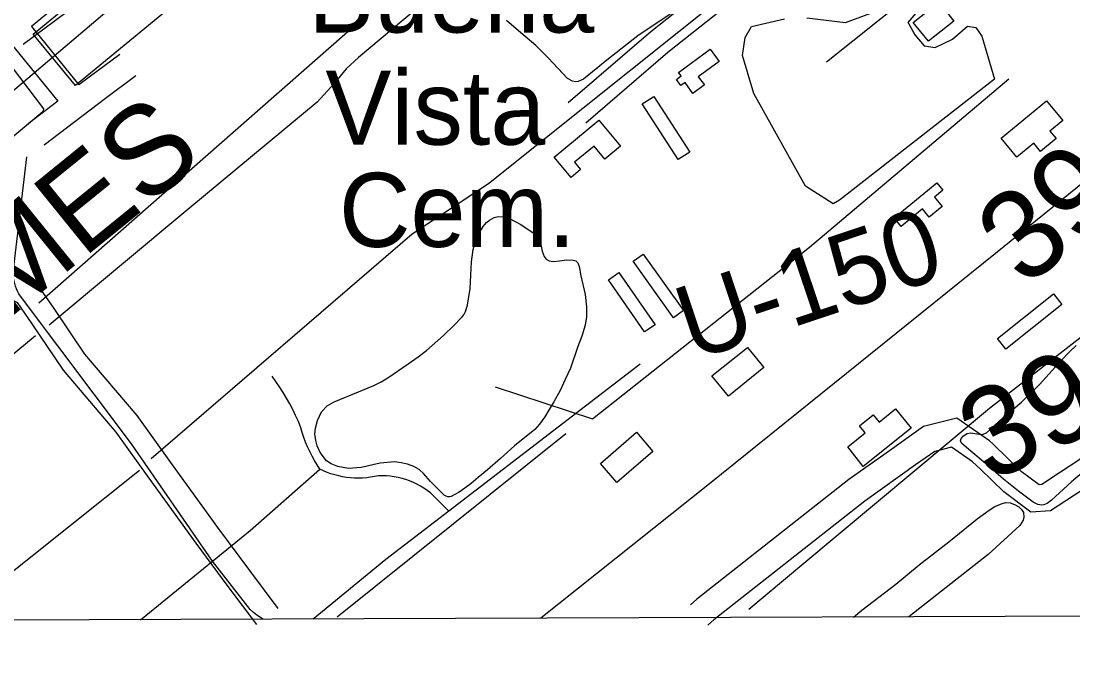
# Model space of a CAD drawing. Extents: x 3392644 to 3430565, y 576657 to 602123.
# Drawn here: x 3410265 to 3411444, y 582044 to 582765 of the extents above; entities that cross this region are included whole.
import ezdxf

# ---------------------------------------------------------------- set-up
doc = ezdxf.new("R2010")
doc.units = 0
for name, color, linetype in [('V-BLDG-OTLN', 7, 'Continuous'), ('V-DTCH-CNTR', 7, 'Continuous'), ('V-GRID-FRAM', 7, 'Continuous'), ('V-RIVR-RANG-IDEN', 7, 'Continuous'), ('V-ROAD-CNTR', 7, 'Continuous'), ('V-SITE-OTLN', 7, 'Continuous'), ('V-SITE-OTLN-IDEN', 7, 'Continuous'), ('V-SITE-VEGE', 7, 'Continuous'), ('V-SURV-IDEN', 7, 'Continuous'), ('V-TOPO-BNDY', 7, 'Continuous'), ('V-TOPO-GNAM-IDEN', 7, 'Continuous'), ('V-TOPO-SHOR', 7, 'Continuous')]:
    doc.layers.add(name, color=color, linetype=linetype)

msp = doc.modelspace()

# ---------------------------------------------------------------- linework, layer by layer
at = {"layer": 'V-BLDG-OTLN'}
for points in [[(3411265.3, 582763.1), (3411293.8, 582785.7), (3411310.7, 582764.5), (3411282.2, 582741.9)], [(3411002.2, 582707), (3411037.6, 582732.9), (3411047.6, 582719.3), (3411024.3, 582702.2), (3411031.1, 582692.9), (3411018.3, 582683.5), (3411009.4, 582695.6), (3411004.9, 582692.3), (3410999.9, 582699.1), (3411005.1, 582703)], [(3410974.3, 582680.2), (3411014.7, 582617.8), (3411001.9, 582609.5), (3410961.5, 582671.9)], [(3411363.9, 582633.2), (3411414.7, 582675.2), (3411432.9, 582653.2), (3411418.4, 582641.2), (3411425.4, 582632.8), (3411408.1, 582618.5), (3411400.5, 582627.7), (3411381.4, 582612)], [(3410862.8, 582612.1), (3410912.9, 582653.4), (3410936.9, 582624.4), (3410919.4, 582609.9), (3410907.4, 582624.4), (3410885.6, 582606.4), (3410892.3, 582598.2), (3410881.6, 582589.3)], [(3411243.7, 582544), (3411291.7, 582583.3), (3411298.5, 582575.1), (3411289.1, 582567.4), (3411297.7, 582556.9), (3411283, 582544.9), (3411275.6, 582554), (3411251.6, 582534.3)], [(3410962.4, 582503.3), (3411007.6, 582440.1), (3410996.6, 582432.2), (3410951.4, 582495.4)], [(3410935.3, 582482.7), (3410975.9, 582424.4), (3410964, 582416.2), (3410923.5, 582474.5)], [(3411431.8, 582447.1), (3411369.2, 582397.1), (3411359.9, 582408.8), (3411422.5, 582458.8)], [(3411039.6, 582367), (3411079.3, 582399), (3411097.6, 582376.3), (3411058, 582344.3)], [(3411262.8, 582308.3), (3411209.2, 582265.7), (3411191.8, 582287.6), (3411211.2, 582303.1), (3411205, 582310.9), (3411220.5, 582323.3), (3411226.9, 582315.3), (3411245.4, 582330.1)], [(3410914.5, 582269), (3410954.9, 582303.8), (3410973.3, 582282.4), (3410932.9, 582247.7)]]:
    msp.add_lwpolyline(points, close=True, dxfattribs=at)
at = {"layer": 'V-DTCH-CNTR'}
for points in [[(3410536.1, 582094.4), (3410533.3, 582096.2), (3410529.4, 582099), (3410525.6, 582102), (3410521.9, 582105.2), (3410479.7, 582159.4), (3410388.7, 582290.8), (3410264.4, 582456.4), (3410262.7, 582459.1), (3410261.2, 582461.8), (3410259.9, 582464.6), (3410258.8, 582467.5), (3410257.9, 582470.4), (3410257.2, 582473.5), (3410256.7, 582476.5), (3410256.4, 582479.6), (3410256.3, 582482.7), (3410256.4, 582485.8), (3410256.8, 582488.9), (3410257.3, 582492), (3410271.4, 582612.6)], [(3410959.1, 582380.1), (3410744.8, 582215.6), (3410673.9, 582161.2), (3410592.6, 582094.6)], [(3410744.8, 582215.6), (3410724, 582236.1), (3410720.4, 582238.8), (3410716.7, 582241.3), (3410712.9, 582243.6), (3410708.9, 582245.7), (3410704.9, 582247.7), (3410700.7, 582249.4), (3410696.5, 582250.9), (3410692.2, 582252.2), (3410687.9, 582253.2), (3410683.5, 582254.1), (3410679, 582254.7), (3410674.6, 582255.1), (3410670.1, 582255.2), (3410665.6, 582255.2), (3410661.2, 582254.2), (3410656.8, 582253.5), (3410652.3, 582252.9), (3410647.9, 582252.6), (3410643.4, 582252.5), (3410638.9, 582252.5), (3410634.4, 582252.8), (3410630, 582253.3), (3410625.5, 582254), (3410621.2, 582254.9), (3410616.8, 582256), (3410612.5, 582257.4), (3410608.3, 582258.9), (3410604.2, 582260.6), (3410600.1, 582262.4), (3410597, 582267.2), (3410594, 582272.1), (3410591.3, 582277.2), (3410588.7, 582282.3), (3410586.3, 582287.5), (3410584.1, 582292.7), (3410582.1, 582298.1), (3410580.3, 582303.5), (3410578.7, 582309), (3410575.9, 582315.9), (3410572.9, 582322.6), (3410569.7, 582329.2), (3410566.3, 582335.7), (3410562.7, 582342.2), (3410558.9, 582348.5), (3410554.9, 582354.7), (3410550.8, 582360.7), (3410546.4, 582366.7)], [(3410399, 582093.9), (3410479.7, 582159.4), (3410522, 582193.7), (3410600.1, 582262.4)]]:
    msp.add_lwpolyline(points, dxfattribs=at)
at = {"layer": 'V-GRID-FRAM'}
msp.add_lwpolyline([(3396720.3, 600227.7), (3428325.7, 600342.6), (3428399.7, 582159.3), (3396778.5, 582044.3), (3396720.3, 600227.7)], dxfattribs=at)
at = {"layer": 'V-ROAD-CNTR'}
for points in [[(3411723.4, 583955), (3411553, 583820.8), (3411271, 583581.5), (3410931.3, 583299.4), (3410595.8, 583021.3), (3410276.6, 582758.6)], [(3411352.3, 583060), (3411234.7, 582961.1), (3410970.9, 582752.3), (3410878.5, 582672.9)], [(3411373.6, 583038.8), (3411253.7, 582937.9), (3410990, 582729.2), (3410898.1, 582650.2)], [(3411902.5, 582930.5), (3411896.5, 582928.3), (3411890.5, 582925.8), (3411884.7, 582923.2), (3411879, 582920.4), (3411873.3, 582917.3), (3411867.8, 582914.1), (3411862.4, 582910.7), (3411857.1, 582907.1), (3411851.9, 582903.4), (3411846.8, 582899.4), (3411841.9, 582895.3), (3411773.2, 582840.3), (3411704.7, 582785.1), (3411636.2, 582729.7), (3411567.9, 582674.2), (3411357.5, 582504), (3411036.7, 582246), (3410847.9, 582095.5)], [(3410148.2, 582867.3), (3410211, 582791.7), (3410306.1, 582674.7)], [(3410276.6, 582758.6), (3410329.9, 582692.9)], [(3410375.8, 582727.1), (3410341.5, 582701.8), (3410329.9, 582692.9)], [(3410393.6, 582703), (3410359.6, 582677.8), (3410291.1, 582625.5)], [(3410306.1, 582674.7), (3410272.9, 582649.4)], [(3410203.4, 582535.8), (3410214.1, 582516.5), (3410225.2, 582497.7), (3410250.9, 582488.1), (3410281.1, 582472.2), (3410301.9, 582442.5), (3410336.2, 582391.5), (3410394.8, 582322.6), (3410432.7, 582270.1), (3410485.2, 582197.3), (3410521, 582149), (3410552.9, 582106.5)], [(3410177.1, 582521.3), (3410188, 582501.5), (3410204.8, 582473.3), (3410238.6, 582460.7), (3410260.7, 582449.1), (3410277.2, 582425.5), (3410312.3, 582373.3), (3410371.2, 582304), (3410408.4, 582252.6), (3410461, 582179.6), (3410496.9, 582131.1), (3410528.9, 582088.5)], [(3411635.1, 582423.7), (3411614.9, 582408.5), (3411523.6, 582332.9), (3411450.8, 582272.5), (3411430.3, 582259)], [(3411354.7, 582290.5), (3411350.8, 582294.2), (3411314.2, 582319.5), (3411276.7, 582310.2), (3411238.5, 582283.1)], [(3411340.6, 582262.4), (3411331.8, 582270.8), (3411308.2, 582287.1), (3411289.4, 582282.5), (3411267.9, 582267.2)], [(3411430.3, 582259), (3411409.4, 582245.2), (3411406.4, 582245), (3411386.3, 582260), (3411354.7, 582290.5)], [(3411238.5, 582283.1), (3411193, 582250.8), (3411022.7, 582116.8), (3411015.5, 582110.7)], [(3411267.9, 582267.2), (3411211, 582226.8), (3411041.6, 582093.6), (3411034.8, 582087.8)], [(3411454.5, 582239), (3411419.1, 582215.7), (3411397.1, 582214.5), (3411366.9, 582237.1), (3411340.6, 582262.4)]]:
    msp.add_lwpolyline(points, dxfattribs=at)
at = {"layer": 'V-SITE-OTLN'}
msp.add_lwpolyline([(3410910, 583172.6), (3410326.2, 582692.2), (3410278.8, 582750), (3410866.1, 583232.3)], close=True, dxfattribs=at)
at = {"layer": 'V-SITE-VEGE'}
for p, q in [((3411364.8, 582224.1), (3411369, 582225.1)), ((3411369, 582225.1), (3411373.8, 582224.9)), ((3411373.8, 582224.9), (3411378.7, 582223.1)), ((3411336.9, 582206.9), (3411350.3, 582216.7)), ((3411350.3, 582216.7), (3411356.6, 582220.8)), ((3411356.6, 582220.8), (3411364.8, 582224.1)), ((3411378.7, 582223.1), (3411383.6, 582220.4)), ((3411383.6, 582220.4), (3411386.8, 582217.4)), ((3411386.8, 582217.4), (3411388.8, 582213.8)), ((3411388.8, 582213.8), (3411389.4, 582208.8)), ((3411305, 582181.2), (3411336.9, 582206.9)), ((3411388.4, 582205.4), (3411384.7, 582199.3)), ((3411389.4, 582208.8), (3411388.4, 582205.4)), ((3411384.7, 582199.3), (3411349.3, 582166.8)), ((3411271.9, 582155.2), (3411305, 582181.2)), ((3411349.3, 582166.8), (3411260.2, 582097)), ((3411245.7, 582133.6), (3411271.9, 582155.2)), ((3411207.5, 582104.4), (3411245.7, 582133.6)), ((3411198.2, 582096.8), (3411207.5, 582104.4)), ((3411260.2, 582097), (3411198.2, 582096.8))]:
    msp.add_line(p, q, dxfattribs=at)
for points in [[(3411296.9, 582807.3), (3411259.1, 582763), (3411260.4, 582761.6), (3411267, 582749.1), (3411277.7, 582736.6), (3411289.9, 582735), (3411309.2, 582744.2), (3411326, 582758.8), (3411335.5, 582757.3), (3411342.1, 582747.6), (3411356.2, 582699.5), (3411182.5, 582563.7), (3411175.6, 582559.7), (3411144.6, 582579.5), (3411086.6, 582683.2), (3411073.8, 582725.8), (3411077, 582746.2), (3411084.1, 582758.4), (3411121.1, 582767.2)], [(3411013.3, 582785.7), (3410972.6, 582758.9), (3410956.6, 582748.1), (3410921.6, 582720.9), (3410895.6, 582699.5), (3410889.8, 582697), (3410886.8, 582696.6), (3410883.1, 582697.1), (3410877.5, 582700.1), (3410856.4, 582723), (3410842.1, 582737.1), (3410825.4, 582751.5), (3410809.3, 582765.2)], [(3411145.8, 582768), (3411189.4, 582763), (3411239, 582781.1)], [(3411488.3, 582286.8), (3411442.8, 582248.3), (3411420.1, 582227.9), (3411415.4, 582224), (3411411.5, 582222.5), (3411409.5, 582222.1), (3411404.9, 582223), (3411399.7, 582225.4), (3411383.2, 582237.8), (3411366.5, 582251.5), (3411346.1, 582268.8), (3411324.8, 582286.8), (3411319.3, 582291.7), (3411318.4, 582294.1), (3411318.9, 582296.7), (3411321.6, 582299.7), (3411325.6, 582302.4), (3411330, 582303.4), (3411336.4, 582302.2), (3411342.7, 582301.2), (3411347.3, 582303.2), (3411350.8, 582306.2), (3411356.8, 582312), (3411365.6, 582320.2), (3411386.5, 582337.7), (3411406.9, 582357.2), (3411421, 582373.2), (3411431.2, 582384.4), (3411440.3, 582393.8), (3411448.1, 582401.1)]]:
    msp.add_lwpolyline(points, dxfattribs=at)
msp.add_lwpolyline([(3410841.2, 582307), (3410818.1, 582288.8), (3410802.5, 582274.5), (3410787.8, 582261.7), (3410777.6, 582253.2), (3410769.5, 582246.6), (3410758.3, 582238.4), (3410755.3, 582236.5), (3410747.4, 582231.9), (3410745.6, 582231.4), (3410743.4, 582231.6), (3410739.8, 582233.1), (3410733.6, 582239), (3410724.2, 582248.8), (3410716.4, 582257.7), (3410711.2, 582262.2), (3410705.3, 582265.6), (3410698.4, 582268.1), (3410691.2, 582269.7), (3410683.6, 582270.6), (3410667.7, 582269.2), (3410646.3, 582264.5), (3410632, 582263.3), (3410620.1, 582265.7), (3410612.8, 582268.5), (3410607.3, 582272), (3410600.5, 582281.3), (3410597.1, 582288.6), (3410595.4, 582294.7), (3410594.3, 582301.6), (3410595.1, 582308.5), (3410597.5, 582317.1), (3410601.9, 582326.9), (3410608.4, 582333.3), (3410616.1, 582338), (3410643.3, 582349.2), (3410660.5, 582356.4), (3410668.7, 582360.4), (3410676.1, 582364.8), (3410699.2, 582380.6), (3410710.2, 582388.3), (3410719.4, 582395.6), (3410738.7, 582412.3), (3410750.1, 582423.3), (3410759.4, 582433.1), (3410761.3, 582435.6), (3410763.3, 582439), (3410765.6, 582446.1), (3410768.6, 582464.9), (3410770.2, 582494.7), (3410771.9, 582508.8), (3410773.8, 582514.8), (3410776.1, 582520), (3410779.6, 582528.6), (3410783, 582534.5), (3410786.7, 582538.7), (3410790.1, 582541.6), (3410795.4, 582544.3), (3410799.9, 582545.6), (3410806, 582545.2), (3410812.6, 582543.3), (3410825.3, 582536.6), (3410843.7, 582524.3), (3410845.7, 582521.2), (3410847.8, 582514.1), (3410849.3, 582506.8), (3410851.4, 582500.9), (3410853.8, 582497.6), (3410857.2, 582495.8), (3410861.5, 582495.1), (3410868.6, 582495.9), (3410876.5, 582497.1), (3410884.1, 582496.8), (3410886.9, 582495.9), (3410889.3, 582493.7), (3410890.8, 582489.7), (3410892.7, 582479.2), (3410897.3, 582458.2), (3410899, 582444.3), (3410899, 582433.1), (3410897.6, 582423.9), (3410893.9, 582411.7), (3410889.4, 582400), (3410881.1, 582375.8), (3410875.2, 582363), (3410869.5, 582350.8), (3410862.4, 582338), (3410857.2, 582329.3), (3410852.2, 582321.2), (3410846.3, 582313)], close=True, dxfattribs=at)
at = {"layer": 'V-TOPO-BNDY'}
msp.add_lwpolyline([(3412089.5, 584240.4), (3409553.2, 582090.8)], dxfattribs=at)
at = {"layer": 'V-TOPO-SHOR'}
for p, q in [((3411167.9, 582719), (3411434.2, 582931)), ((3410267.5, 582738.8), (3410316.8, 582775.3)), ((3410285.1, 582448.7), (3410643.4, 582763.2)), ((3410619.4, 582097), (3410875.9, 582302.4)), ((3410397.9, 582261.1), (3410194, 582098.8))]:
    msp.add_line(p, q, dxfattribs=at)
for points in [[(3410411, 582274.3), (3410703.6, 582526), (3410789.1, 582582.4), (3411108.1, 582837.5), (3411288.9, 582993.1), (3411344.8, 583032.9)], [(3410922.8, 582954), (3410862, 582907), (3410747.1, 582811), (3410643.5, 582723.7), (3410629.4, 582710.9), (3410616, 582694.7), (3410597, 582673.7), (3410452.1, 582553.5), (3410296.6, 582423.9)], [(3410150.5, 582861.6), (3410145.6, 582857), (3410146.9, 582854.9), (3410290.3, 582666.2), (3410289.6, 582662.8), (3410172.4, 582565.2), (3409900.5, 582336.5), (3409641.1, 582119.8), (3409606.6, 582091)], [(3411896.5, 582754.6), (3411350.6, 582330.5), (3411140.2, 582155), (3411081.1, 582105.3)], [(3410796.5, 582354.9), (3410905.5, 582319), (3411148.8, 582511.2), (3411372.4, 582699.9)], [(3410281.2, 582411.9), (3410068.3, 582235.3), (3409892.6, 582092)]]:
    msp.add_lwpolyline(points, dxfattribs=at)

# ---------------------------------------------------------------- texts
at = {"layer": 'V-RIVR-RANG-IDEN'}
msp.add_text('U-150', height=83, rotation=18.5163, dxfattribs=at).set_placement((3411017.6, 582383.4))
at = {"layer": 'V-SITE-OTLN-IDEN'}
for s, p in [('Buena', (3410586.8, 582751.7)), ('Vista', (3410606.2, 582626)), ('Cem.', (3410621.5, 582511.5))]:
    msp.add_text(s, height=83, dxfattribs=at).set_placement(p)
at = {"layer": 'V-SURV-IDEN'}
for s, rotation, p in [('390+14.4', 39.3224, (3411390.6, 582464.5)), ('392+82.9', 27.0365, (3411351, 582245.9))]:
    msp.add_text(s, height=100, rotation=rotation, dxfattribs=at).set_placement(p)
at = {"layer": 'V-TOPO-GNAM-IDEN'}
msp.add_text('ST.  JAMES', height=100, rotation=39.0222, dxfattribs=at).set_placement((3409907, 582151.6))

doc.saveas('drawing.dxf')
